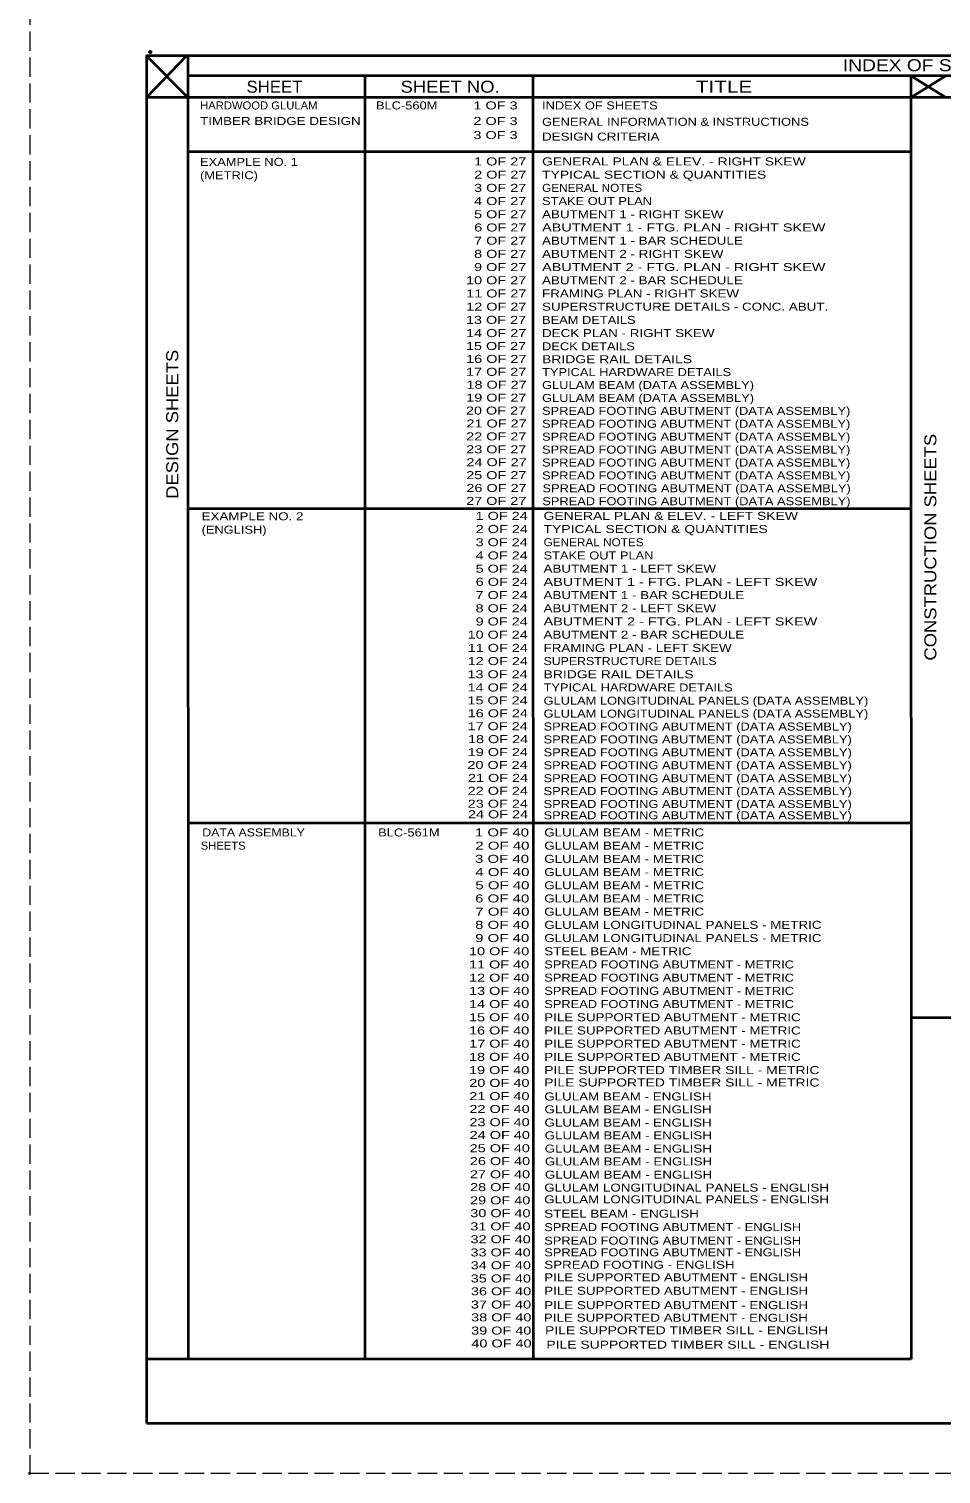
# Model space of a CAD drawing. Extents: x 0 to 68, y -44 to 0.
# Drawn here: x -0.01 to 13.66, y -44.01 to -22.35 of the extents above; entities that cross this region are included whole.
import ezdxf
from ezdxf.enums import TextEntityAlignment as Align

# ---------------------------------------------------------------- set-up
doc = ezdxf.new("R2010")
doc.units = 0
doc.header["$LTSCALE"] = 0.048
doc.header["$PDMODE"] = 32
doc.header["$PDSIZE"] = 0.024
doc.linetypes.add('LONG_DASHED', pattern=[7.5, 6, -1.5])
for name, color, linetype, lineweight in [('1', 7, 'Continuous', 25), ('2', 7, 'Continuous', 35), ('4', 7, 'Continuous', 35), ('6', 7, 'Continuous', 35), ('63', 7, 'LONG_DASHED', 13)]:
    doc.layers.add(name, color=color, linetype=linetype, lineweight=lineweight)
doc.layers.add('62', color=7, linetype='Continuous')

msp = doc.modelspace()

# ---------------------------------------------------------------- linework, layer by layer
at = {"layer": '1', "lineweight": 35}
msp.add_lwpolyline([(1.75, -43.25), (33.25, -43.25), (33.25, -22.75), (1.75, -22.75)], close=True, dxfattribs=at)
at = {"layer": '2'}
msp.add_point((1.80733, -22.69433), dxfattribs=at)
at = {"layer": '4'}
for p, q in [((1.75, -22.75), (2.3725, -23.37517)), ((2.35333, -22.75), (1.75, -23.37517)), ((2.3725, -22.75), (2.37567, -42.28983)), ((5.02375, -23.05267), (5.02692, -42.28983)), ((7.54542, -23.05267), (7.54858, -42.28983)), ((13.21158, -23.05267), (13.21475, -42.28983)), ((13.21158, -23.05267), (13.73333, -23.37517)), ((13.73333, -23.05267), (13.21158, -23.37517)), ((14.2795, -23.37517), (1.75, -23.37517)), ((24.52058, -23.37517), (13.21158, -23.37517)), ((13.21158, -24.19058), (2.3725, -24.19058)), ((13.21267, -29.54142), (2.37567, -29.54142)), ((13.21475, -34.25333), (2.37567, -34.25333)), ((24.52058, -37.17283), (13.21392, -37.17283)), ((13.21475, -42.28983), (1.75, -42.28983))]:
    msp.add_line(p, q, dxfattribs=at)
at = {"layer": '6'}
msp.add_line((24.52058, -23.05267), (2.3725, -23.05267), dxfattribs=at)
at = {"layer": '62'}
msp.add_point((0, -44), dxfattribs=at)
at = {"layer": '63'}
msp.add_lwpolyline([(0, -44), (34, -44), (34, -22), (0, -22)], close=True, dxfattribs=at)

# ---------------------------------------------------------------- texts
at = {"layer": '2'}
for s, width, p in [('INDEX OF SHEETS', 1.2, (13.48658, -22.98092)), ('SHEET', 1.05, (3.66971, -23.30342)), ('SHEET NO.', 1.15, (6.30279, -23.30342)), ('TITLE', 1.3, (10.41067, -23.30342))]:
    msp.add_text(s, height=0.1792, dxfattribs=dict(at, width=width)).set_placement(p, align=Align.CENTER)
for s, width, p in [('HARDWOOD GLULAM', 1.05, (2.55475, -23.5545)), ('BLC-560M', 1.2, (5.192, -23.5545)), ('INDEX OF SHEETS', 1.2, (7.68192, -23.5545)), ('TIMBER BRIDGE DESIGN', 1.25, (2.55475, -23.78742)), ('GENERAL INFORMATION & INSTRUCTIONS', 1.2, (7.68192, -23.79983)), ('DESIGN CRITERIA', 1.25, (7.68192, -24.02175)), ('(METRIC)', 1.2, (2.55475, -24.601)), ('EXAMPLE NO. 1', 1.2, (2.55475, -24.401)), ('TYPICAL SECTION & QUANTITIES', 1.3, (7.68192, -24.592)), ('GENERAL PLAN & ELEV. - RIGHT SKEW', 1.3, (7.68192, -24.39408)), ('GENERAL NOTES', 1.1, (7.68192, -24.78992)), ('STAKE OUT PLAN', 1.2, (7.68192, -24.98783)), ('ABUTMENT 1 - RIGHT SKEW', 1.25, (7.68192, -25.18575)), ('ABUTMENT 1 - FTG. PLAN - RIGHT SKEW', 1.35, (7.68192, -25.38375)), ('ABUTMENT 1 - BAR SCHEDULE', 1.25, (7.68192, -25.58158)), ('ABUTMENT 2 - RIGHT SKEW', 1.25, (7.68192, -25.77958)), ('ABUTMENT 2 - FTG. PLAN - RIGHT SKEW', 1.35, (7.68192, -25.9775)), ('ABUTMENT 2 - BAR SCHEDULE', 1.25, (7.68192, -26.17542)), ('FRAMING PLAN - RIGHT SKEW', 1.25, (7.68192, -26.37333)), ('SUPERSTRUCTURE DETAILS - CONC. ABUT.', 1.25, (7.68192, -26.57125)), ('BEAM DETAILS', 1.2, (7.68192, -26.76917)), ('DECK PLAN - RIGHT SKEW', 1.25, (7.68192, -26.96708)), ('DECK DETAILS', 1.2, (7.68192, -27.165)), ('BRIDGE RAIL DETAILS', 1.3, (7.68192, -27.35858)), ('TYPICAL HARDWARE DETAILS', 1.2, (7.68192, -27.55217)), ('GLULAM BEAM (DATA ASSEMBLY)', 1.2, (7.68192, -27.74583)), ('GLULAM BEAM (DATA ASSEMBLY)', 1.2, (7.68192, -27.93942)), ('SPREAD FOOTING ABUTMENT (DATA ASSEMBLY)', 1.2, (7.68192, -28.133)), ('SPREAD FOOTING ABUTMENT (DATA ASSEMBLY)', 1.2, (7.68192, -28.32667)), ('SPREAD FOOTING ABUTMENT (DATA ASSEMBLY)', 1.2, (7.68192, -28.52025)), ('SPREAD FOOTING ABUTMENT (DATA ASSEMBLY)', 1.2, (7.68192, -28.71392)), ('SPREAD FOOTING ABUTMENT (DATA ASSEMBLY)', 1.2, (7.68192, -28.9075)), ('SPREAD FOOTING ABUTMENT (DATA ASSEMBLY)', 1.2, (7.68192, -29.10108)), ('SPREAD FOOTING ABUTMENT (DATA ASSEMBLY)', 1.2, (7.68875, -29.29367)), ('SPREAD FOOTING ABUTMENT (DATA ASSEMBLY)', 1.2, (7.68508, -29.48733)), ('EXAMPLE NO. 2', 1.25, (2.57725, -29.71375)), ('GENERAL PLAN & ELEV. - LEFT SKEW', 1.3, (7.70442, -29.70683)), ('(ENGLISH)', 1.2, (2.57725, -29.91375)), ('TYPICAL SECTION & QUANTITIES', 1.3, (7.70442, -29.90475)), ('GENERAL NOTES', 1.1, (7.70442, -30.10267)), ('STAKE OUT PLAN', 1.2, (7.70442, -30.30058)), ('ABUTMENT 1 - LEFT SKEW', 1.25, (7.70442, -30.4985)), ('ABUTMENT 1 - FTG. PLAN - LEFT SKEW', 1.35, (7.70442, -30.6965)), ('ABUTMENT 1 - BAR SCHEDULE', 1.25, (7.70442, -30.89433)), ('ABUTMENT 2 - LEFT SKEW', 1.25, (7.70442, -31.09233)), ('ABUTMENT 2 - FTG. PLAN - LEFT SKEW', 1.35, (7.70442, -31.29025)), ('ABUTMENT 2 - BAR SCHEDULE', 1.25, (7.70442, -31.48817)), ('FRAMING PLAN - LEFT SKEW', 1.25, (7.70442, -31.68608)), ('SUPERSTRUCTURE DETAILS', 1.15, (7.70442, -31.884)), ('BRIDGE RAIL DETAILS', 1.3, (7.70442, -32.08192)), ('TYPICAL HARDWARE DETAILS', 1.2, (7.70442, -32.27983)), ('GLULAM LONGITUDINAL PANELS (DATA ASSEMBLY)', 1.2, (7.70442, -32.47775)), ('GLULAM LONGITUDINAL PANELS (DATA ASSEMBLY)', 1.2, (7.70442, -32.67133)), ('SPREAD FOOTING ABUTMENT (DATA ASSEMBLY)', 1.2, (7.70442, -32.86492)), ('SPREAD FOOTING ABUTMENT (DATA ASSEMBLY)', 1.2, (7.70442, -33.05858)), ('SPREAD FOOTING ABUTMENT (DATA ASSEMBLY)', 1.2, (7.70442, -33.25217)), ('SPREAD FOOTING ABUTMENT (DATA ASSEMBLY)', 1.2, (7.70442, -33.44575)), ('SPREAD FOOTING ABUTMENT (DATA ASSEMBLY)', 1.2, (7.70442, -33.63942)), ('SPREAD FOOTING ABUTMENT (DATA ASSEMBLY)', 1.2, (7.70442, -33.833)), ('SPREAD FOOTING ABUTMENT (DATA ASSEMBLY)', 1.2, (7.70442, -34.02667)), ('SPREAD FOOTING ABUTMENT (DATA ASSEMBLY)', 1.2, (7.70442, -34.19575)), ('DATA ASSEMBLY', 1.15, (2.5875, -34.45292)), ('BLC-561M', 1.2, (5.22475, -34.45292)), ('GLULAM BEAM - METRIC', 1.25, (7.71467, -34.45292)), ('SHEETS', 1.05, (2.563, -34.65083)), ('GLULAM BEAM - METRIC', 1.25, (7.71467, -34.65083)), ('GLULAM BEAM - METRIC', 1.25, (7.71467, -34.84875)), ('GLULAM BEAM - METRIC', 1.25, (7.71467, -35.04667)), ('GLULAM BEAM - METRIC', 1.25, (7.71467, -35.24458)), ('GLULAM BEAM - METRIC', 1.25, (7.71467, -35.4425)), ('GLULAM BEAM - METRIC', 1.25, (7.71467, -35.64042)), ('GLULAM LONGITUDINAL PANELS - METRIC', 1.25, (7.71467, -35.83833)), ('GLULAM LONGITUDINAL PANELS - METRIC', 1.25, (7.71467, -36.03625)), ('STEEL BEAM - METRIC', 1.25, (7.71467, -36.23417)), ('SPREAD FOOTING ABUTMENT - METRIC', 1.2, (7.71467, -36.43208)), ('SPREAD FOOTING ABUTMENT - METRIC', 1.2, (7.71467, -36.63)), ('SPREAD FOOTING ABUTMENT - METRIC', 1.2, (7.71467, -36.82792)), ('SPREAD FOOTING ABUTMENT - METRIC', 1.2, (7.71467, -37.02583)), ('PILE SUPPORTED ABUTMENT - METRIC', 1.25, (7.71467, -37.22375)), ('PILE SUPPORTED ABUTMENT - METRIC', 1.25, (7.71467, -37.42167)), ('PILE SUPPORTED ABUTMENT - METRIC', 1.25, (7.71467, -37.61958)), ('PILE SUPPORTED ABUTMENT - METRIC', 1.25, (7.71467, -37.8175)), ('PILE SUPPORTED TIMBER SILL - METRIC', 1.3, (7.71467, -38.01542)), ('PILE SUPPORTED TIMBER SILL - METRIC', 1.3, (7.71467, -38.20142)), ('GLULAM BEAM - ENGLISH', 1.25, (7.71467, -38.41125)), ('GLULAM BEAM - ENGLISH', 1.25, (7.71783, -38.60383)), ('GLULAM BEAM - ENGLISH', 1.25, (7.71783, -38.80175)), ('GLULAM BEAM - ENGLISH', 1.25, (7.721, -38.99433)), ('GLULAM BEAM - ENGLISH', 1.25, (7.721, -39.19225)), ('GLULAM BEAM - ENGLISH', 1.25, (7.72417, -39.38483)), ('GLULAM BEAM - ENGLISH', 1.25, (7.72417, -39.58275)), ('GLULAM LONGITUDINAL PANELS - ENGLISH', 1.25, (7.71458, -39.77725)), ('GLULAM LONGITUDINAL PANELS - ENGLISH', 1.25, (7.71458, -39.95308)), ('STEEL BEAM - ENGLISH', 1.25, (7.71458, -40.16775)), ('SPREAD FOOTING ABUTMENT - ENGLISH', 1.2, (7.71458, -40.36967)), ('SPREAD FOOTING ABUTMENT - ENGLISH', 1.2, (7.71458, -40.57158)), ('SPREAD FOOTING ABUTMENT - ENGLISH', 1.2, (7.71458, -40.74742)), ('SPREAD FOOTING - ENGLISH', 1.25, (7.71458, -40.9335)), ('PILE SUPPORTED ABUTMENT - ENGLISH', 1.25, (7.71458, -41.12242)), ('PILE SUPPORTED ABUTMENT - ENGLISH', 1.25, (7.71458, -41.32433)), ('PILE SUPPORTED ABUTMENT - ENGLISH', 1.25, (7.71458, -41.53933)), ('PILE SUPPORTED ABUTMENT - ENGLISH', 1.25, (7.71058, -41.72783)), ('PILE SUPPORTED TIMBER SILL - ENGLISH', 1.3, (7.72675, -41.91633)), ('PILE SUPPORTED TIMBER SILL - ENGLISH', 1.3, (7.74633, -42.13133))]:
    msp.add_text(s, height=0.12, dxfattribs=dict(at, width=width)).set_placement(p)
for s, width, p in [('1 OF 3', 1.35, (7.315, -23.5545)), ('2 OF 3', 1.35, (7.315, -23.78742)), ('3 OF 3', 1.35, (7.315, -23.99775)), ('2 OF 27', 1.35, (7.44708, -24.592)), ('1 OF 27', 1.35, (7.44525, -24.39408)), ('3 OF 27', 1.35, (7.44525, -24.78992)), ('4 OF 27', 1.35, (7.44525, -24.98783)), ('5 OF 27', 1.35, (7.44525, -25.18575)), ('6 OF 27', 1.35, (7.44708, -25.38375)), ('7 OF 27', 1.35, (7.44525, -25.58158)), ('8 OF 27', 1.35, (7.44525, -25.77958)), ('9 OF 27', 1.35, (7.44525, -25.9775)), ('10 OF 27', 1.35, (7.44533, -26.17542)), ('11 OF 27', 1.35, (7.44717, -26.37333)), ('13 OF 27', 1.35, (7.4435, -26.76917)), ('12 OF 27', 1.35, (7.44717, -26.57125)), ('14 OF 27', 1.35, (7.44533, -26.96708)), ('15 OF 27', 1.35, (7.4435, -27.16067)), ('16 OF 27', 1.35, (7.44717, -27.35425)), ('17 OF 27', 1.35, (7.44533, -27.54792)), ('18 OF 27', 1.35, (7.451, -27.7415)), ('19 OF 27', 1.35, (7.44733, -27.93508)), ('20 OF 27', 1.35, (7.44358, -28.12875)), ('21 OF 27', 1.35, (7.451, -28.32233)), ('22 OF 27', 1.35, (7.44725, -28.516)), ('23 OF 27', 1.35, (7.44725, -28.70958)), ('24 OF 27', 1.35, (7.45092, -28.90317)), ('25 OF 27', 1.35, (7.44725, -29.09683)), ('26 OF 27', 1.35, (7.45042, -29.28933)), ('27 OF 27', 1.35, (7.44675, -29.483)), ('1 OF 24', 1.35, (7.46775, -29.70683)), ('2 OF 24', 1.35, (7.46958, -29.90475)), ('3 OF 24', 1.35, (7.46775, -30.10267)), ('4 OF 24', 1.35, (7.46775, -30.30058)), ('5 OF 24', 1.35, (7.46775, -30.4985)), ('6 OF 24', 1.35, (7.46958, -30.6965)), ('8 OF 24', 1.35, (7.46775, -31.09233)), ('7 OF 24', 1.35, (7.46775, -30.89433)), ('9 OF 24', 1.35, (7.46775, -31.29025)), ('10 OF 24', 1.35, (7.46783, -31.48817)), ('11 OF 24', 1.35, (7.46967, -31.68608)), ('12 OF 24', 1.35, (7.46967, -31.884)), ('13 OF 24', 1.35, (7.466, -32.08192)), ('14 OF 24', 1.35, (7.46783, -32.27983)), ('15 OF 24', 1.35, (7.466, -32.47342)), ('16 OF 24', 1.35, (7.46967, -32.667)), ('17 OF 24', 1.35, (7.46783, -32.86067)), ('19 OF 24', 1.35, (7.46983, -33.24783)), ('18 OF 24', 1.35, (7.4735, -33.05425)), ('20 OF 24', 1.35, (7.46608, -33.4415)), ('21 OF 24', 1.35, (7.4735, -33.63508)), ('22 OF 24', 1.35, (7.46975, -33.82875)), ('23 OF 24', 1.35, (7.46975, -34.02233)), ('24 OF 24', 1.35, (7.47342, -34.18008)), ('1 OF 40', 1.4, (7.4865, -34.45292)), ('2 OF 40', 1.4, (7.49283, -34.65083)), ('3 OF 40', 1.4, (7.4875, -34.84875)), ('4 OF 40', 1.4, (7.49283, -35.04667)), ('5 OF 40', 1.4, (7.49283, -35.24458)), ('6 OF 40', 1.4, (7.49017, -35.4425)), ('7 OF 40', 1.4, (7.49283, -35.64042)), ('8 OF 40', 1.4, (7.49017, -35.83833)), ('9 OF 40', 1.4, (7.49017, -36.03625)), ('10 OF 40', 1.35, (7.48992, -36.23417)), ('11 OF 40', 1.35, (7.48883, -36.43208)), ('12 OF 40', 1.35, (7.48992, -36.63)), ('13 OF 40', 1.35, (7.48992, -36.82792)), ('14 OF 40', 1.35, (7.48992, -37.02583)), ('15 OF 40', 1.35, (7.48992, -37.22375)), ('16 OF 40', 1.35, (7.48992, -37.42167)), ('18 OF 40', 1.35, (7.48992, -37.8175)), ('17 OF 40', 1.35, (7.49258, -37.61958)), ('19 OF 40', 1.35, (7.48992, -38.01542)), ('20 OF 40', 1.35, (7.49308, -38.208)), ('21 OF 40', 1.35, (7.49308, -38.40592)), ('22 OF 40', 1.35, (7.49625, -38.5985)), ('23 OF 40', 1.35, (7.49625, -38.79642)), ('24 OF 40', 1.35, (7.49942, -38.989)), ('25 OF 40', 1.35, (7.49942, -39.18692)), ('26 OF 40', 1.35, (7.50258, -39.3795)), ('27 OF 40', 1.35, (7.50258, -39.57742)), ('28 OF 40', 1.35, (7.50575, -39.77)), ('29 OF 40', 1.35, (7.50575, -39.96792)), ('30 OF 40', 1.35, (7.50892, -40.1605)), ('31 OF 40', 1.35, (7.50892, -40.35842)), ('32 OF 40', 1.35, (7.51208, -40.551)), ('33 OF 40', 1.35, (7.51208, -40.74892)), ('34 OF 40', 1.35, (7.51525, -40.9415)), ('35 OF 40', 1.35, (7.51525, -41.13942)), ('36 OF 40', 1.35, (7.51842, -41.332)), ('37 OF 40', 1.35, (7.51842, -41.52992)), ('38 OF 40', 1.35, (7.52158, -41.7225)), ('39 OF 40', 1.35, (7.52158, -41.92042)), ('40 OF 40', 1.35, (7.52475, -42.113))]:
    msp.add_text(s, height=0.12, dxfattribs=dict(at, width=width)).set_placement(p, align=Align.RIGHT)
at = {"layer": '2', "width": 1.15}
for s, p in [('DESIGN SHEETS', (2.22608, -28.27483)), ('CONSTRUCTION SHEETS', (13.59358, -30.11725))]:
    msp.add_text(s, height=0.1792, rotation=90, dxfattribs=at).set_placement(p, align=Align.CENTER)

doc.saveas('drawing.dxf')
